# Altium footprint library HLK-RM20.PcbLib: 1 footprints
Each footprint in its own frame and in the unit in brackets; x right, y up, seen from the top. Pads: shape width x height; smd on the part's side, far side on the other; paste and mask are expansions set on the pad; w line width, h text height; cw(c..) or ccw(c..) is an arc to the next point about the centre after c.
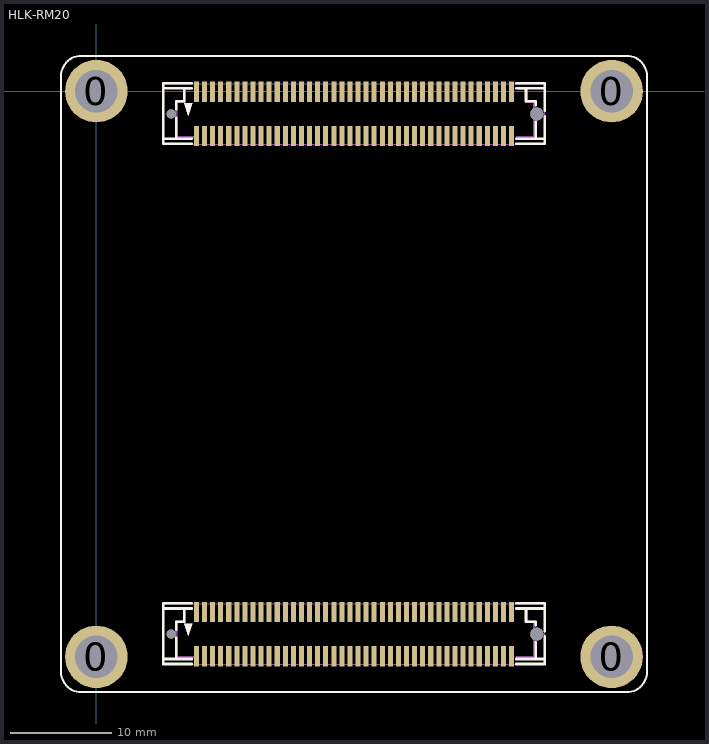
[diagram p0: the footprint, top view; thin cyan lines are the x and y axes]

## HLK-RM20 [mm]
pads (168):
  round 6.2 hole 4.2: 0(0,-56) 0(0,0) 0(51,-56) 0(51,0)
  rect 0.5x2 smd paste+0 mask+0.051: A1(9.9,-51.55) A2(9.9,-55.95) A3(10.7,-51.55) A4(10.7,-55.95) A5(11.5,-51.55) A6(11.5,-55.95) A7(12.3,-51.55) A8(12.3,-55.95) A9(13.1,-51.55) A10(13.1,-55.95) A11(13.9,-51.55) A12(13.9,-55.95) A13(14.7,-51.55) A14(14.7,-55.95) A15(15.5,-51.55) A16(15.5,-55.95) A17(16.3,-51.55) A18(16.3,-55.95) A19(17.1,-51.55) A20(17.1,-55.95) A21(17.9,-51.55) A22(17.9,-55.95) A23(18.7,-51.55) A24(18.7,-55.95) A25(19.5,-51.55) A26(19.5,-55.95) A27(20.3,-51.55) A28(20.3,-55.95) A29(21.1,-51.55) A30(21.1,-55.95) A31(21.9,-51.55) A32(21.9,-55.95) A33(22.7,-51.55) A34(22.7,-55.95) A35(23.5,-51.55) A36(23.5,-55.95) A37(24.3,-51.55) A38(24.3,-55.95) A39(25.1,-51.55) A40(25.1,-55.95) A41(25.9,-51.55) A42(25.9,-55.95) A43(26.7,-51.55) A44(26.7,-55.95) A45(27.5,-51.55) A46(27.5,-55.95) A47(28.3,-51.55) A48(28.3,-55.95) A49(29.1,-51.55) A50(29.1,-55.95) A51(29.9,-51.55) A52(29.9,-55.95) A53(30.7,-51.55) A54(30.7,-55.95) A55(31.5,-51.55) A56(31.5,-55.95) A57(32.3,-51.55) A58(32.3,-55.95) A59(33.1,-51.55) A60(33.1,-55.95) A61(33.9,-51.55) A62(33.9,-55.95) A63(34.7,-51.55) A64(34.7,-55.95) A65(35.5,-51.55) A66(35.5,-55.95) A67(36.3,-51.55) A68(36.3,-55.95) A69(37.1,-51.55) A70(37.1,-55.95) A71(37.9,-51.55) A72(37.9,-55.95) A73(38.7,-51.55) A74(38.7,-55.95) A75(39.5,-51.55) A76(39.5,-55.95) A77(40.3,-51.55) A78(40.3,-55.95) A79(41.1,-51.55) A80(41.1,-55.95) B1(9.9,-0.05) B2(9.9,-4.45) B3(10.7,-0.05) B4(10.7,-4.45) B5(11.5,-0.05) B6(11.5,-4.45) B7(12.3,-0.05) B8(12.3,-4.45) B9(13.1,-0.05) B10(13.1,-4.45) B11(13.9,-0.05) B12(13.9,-4.45) B13(14.7,-0.05) B14(14.7,-4.45) B15(15.5,-0.05) B16(15.5,-4.45) B17(16.3,-0.05) B18(16.3,-4.45) B19(17.1,-0.05) B20(17.1,-4.45) B21(17.9,-0.05) B22(17.9,-4.45) B23(18.7,-0.05) B24(18.7,-4.45) B25(19.5,-0.05) B26(19.5,-4.45) B27(20.3,-0.05) B28(20.3,-4.45) B29(21.1,-0.05) B30(21.1,-4.45) B31(21.9,-0.05) B32(21.9,-4.45) B33(22.7,-0.05) B34(22.7,-4.45) B35(23.5,-0.05) B36(23.5,-4.45) B37(24.3,-0.05) B38(24.3,-4.45) B39(25.1,-0.05) B40(25.1,-4.45) B41(25.9,-0.05) B42(25.9,-4.45) B43(26.7,-0.05) B44(26.7,-4.45) B45(27.5,-0.05) B46(27.5,-4.45) B47(28.3,-0.05) B48(28.3,-4.45) B49(29.1,-0.05) B50(29.1,-4.45) B51(29.9,-0.05) B52(29.9,-4.45) B53(30.7,-0.05) B54(30.7,-4.45) B55(31.5,-0.05) B56(31.5,-4.45) B57(32.3,-0.05) B58(32.3,-4.45) B59(33.1,-0.05) B60(33.1,-4.45) B61(33.9,-0.05) B62(33.9,-4.45) B63(34.7,-0.05) B64(34.7,-4.45) B65(35.5,-0.05) B66(35.5,-4.45) B67(36.3,-0.05) B68(36.3,-4.45) B69(37.1,-0.05) B70(37.1,-4.45) B71(37.9,-0.05) B72(37.9,-4.45) B73(38.7,-0.05) B74(38.7,-4.45) B75(39.5,-0.05) B76(39.5,-4.45) B77(40.3,-0.05) B78(40.3,-4.45) B79(41.1,-0.05) B80(41.1,-4.45)
  round 0.9 hole 0.9 unplated: ""(7.4,-53.75) ""(7.4,-2.25)
  round 1.3 hole 1.3 unplated: ""(43.6,-53.75) ""(43.6,-2.25)
Top Overlay:
  region: 8.7,-1.213 9.5,-1.213 9.1,-2.413
  region: 8.7,-52.713 9.5,-52.713 9.1,-53.913
  lines w0.2: -3.5,-57.5 ccw(c-1.5,-57.5) -1.5,-59.5 52.5,-59.5 ccw(c52.5,-57.5) 54.5,-57.5 54.5,1.5 ccw(c52.5,1.5) 52.5,3.5 -1.5,3.5 ccw(c-1.5,1.5) -3.5,1.5 -3.5,-57.5
  lines w0.254: 6.6,-56.213 9.419,-56.213 ; 6.6,-51.213 9.419,-51.213 ; 6.6,-4.713 9.419,-4.713 ; 6.6,0.287 9.419,0.287 ; 7.898,-56.213 7.9,-55.813 7.9,-54.116 ; 7.898,-4.713 7.9,-4.313 7.9,-2.616 ; 7.9,-53.31 7.9,-52.513 8.7,-52.513 8.7,-51.213 ; 7.9,-1.81 7.9,-1.013 8.7,-1.013 8.7,0.287 ; 9.419,-56.713 6.6,-56.713 6.6,-50.713 9.419,-50.713 ; 9.419,-5.213 6.6,-5.213 6.6,0.787 9.419,0.787 ; 41.581,-56.713 44.4,-56.713 44.4,-53.973 ; 41.581,-56.213 44.4,-56.213 ; 41.581,-51.213 44.4,-51.213 ; 41.581,-50.713 44.4,-50.713 44.4,-53.452 ; 41.581,-5.213 44.4,-5.213 44.4,-2.473 ; 41.581,-4.713 44.4,-4.713 ; 41.581,0.287 44.4,0.287 ; 41.581,0.787 44.4,0.787 44.4,-1.952 ; 42.53,-51.213 42.53,-52.513 43.5,-52.513 43.5,-52.876 ; 42.53,0.287 42.53,-1.013 43.5,-1.013 43.5,-1.376 ; 43.5,-56.213 43.5,-54.55 ; 43.5,-4.713 43.5,-3.05
Mechanical 6:
  region: 41.75,0.35 42.65,0.35 42.65,-0.95 43.45,-0.95 43.45,-1.05 43.45,-4.65 41.55,-4.65 41.55,-4.45 43.25,-4.45 43.25,-1.15 42.45,-1.15 42.45,0.05 42.45,0.15 41.75,0.15
  region: 9.5,0.35 8.6,0.35 8.6,-0.95 7.8,-0.95 7.8,-1.05 7.8,-4.65 9.7,-4.65 9.7,-4.45 8,-4.45 8,-1.15 8.8,-1.15 8.8,0.05 8.8,0.15 9.5,0.15
  region: 8.7,-1.217 9.5,-1.217 9.1,-2.417
  region: 41.75,-51.15 42.65,-51.15 42.65,-52.45 43.45,-52.45 43.45,-52.55 43.45,-56.15 41.55,-56.15 41.55,-55.95 43.25,-55.95 43.25,-52.65 42.45,-52.65 42.45,-51.45 42.45,-51.35 41.75,-51.35
  region: 9.5,-51.15 8.6,-51.15 8.6,-52.45 7.8,-52.45 7.8,-52.55 7.8,-56.15 9.7,-56.15 9.7,-55.95 8,-55.95 8,-52.65 8.8,-52.65 8.8,-51.45 8.8,-51.35 9.5,-51.35
  region: 8.7,-52.717 9.5,-52.717 9.1,-53.917
Mechanical 15:
  drawing of 168 lines, arcs and shapes, not listed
